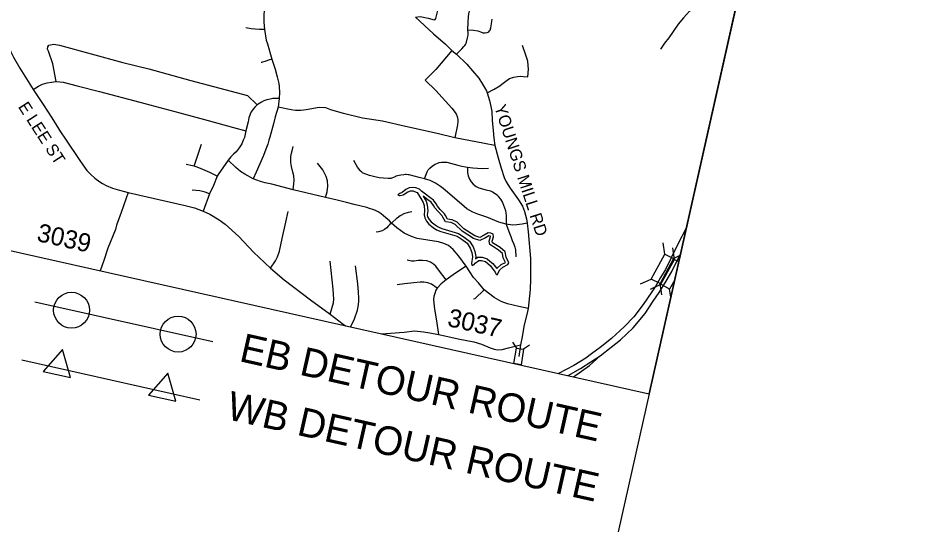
# Model space of a CAD drawing. Extents: x 1784499 to 1786147, y 841097 to 842538.
# Drawn here: x 1784767.1 to 1785099.6, y 841925.9 to 842114.2 of the extents above; entities that cross this region are included whole.
import ezdxf

# ---------------------------------------------------------------- set-up
doc = ezdxf.new("R2010")
doc.units = 0
for name, color, linetype in [('DEV CONE PLAN VIEW CELL', 7, 'Continuous'), ('Exist Hydrographic Buffer Line', 7, 'Continuous'), ('Exist Hydrographic Pond Over 1500 Sq Ft', 7, 'Continuous'), ('Exist Road Primary Interstate Divided Center Attributed', 7, 'Continuous'), ('Exist Road Primary Interstate Ramp 1 Lane Attributed', 7, 'Continuous'), ('Exist Road Primary Interstate Structure Standard Bridge CELL', 7, 'Continuous'), ('Exist Road Secondary Structure Standard Bridge CELL', 7, 'Continuous'), ('Exist Road Secondary Type 51 Attributed', 7, 'Continuous'), ('Exist Road Secondary Type 51 Number Label', 7, 'Continuous'), ('Old_Level_1', 7, 'Continuous'), ('Old_Level_40', 7, 'Continuous'), ('Prop DSN Text', 7, 'Continuous'), ('Scratch_Level_3', 7, 'Continuous')]:
    doc.layers.add(name, color=color, linetype=linetype)

msp = doc.modelspace()

# ---------------------------------------------------------------- linework, layer by layer
at = {"layer": 'DEV CONE PLAN VIEW CELL'}
for points in [[(1784783.32, 841992.77), (1784776.29, 841984.74), (1784786.25, 841982.51)], [(1784821.9, 841984.12), (1784814.88, 841976.09), (1784824.83, 841973.85)]]:
    msp.add_lwpolyline(points, close=True, dxfattribs=at)
at = {"layer": 'Exist Hydrographic Buffer Line'}
for points in [[(1784915.51, 842048.94), (1784916.53, 842047.14), (1784916.96, 842045.79), (1784917.14, 842043.62), (1784916.96, 842042.12), (1784917.12, 842041.38), (1784917.64, 842040.4), (1784918.38, 842039.53), (1784919.81, 842038.41), (1784920.91, 842037.68), (1784922.33, 842037.07), (1784928.39, 842035.33), (1784930.45, 842033.98), (1784932.41, 842032.52), (1784933.75, 842030.41), (1784934.4, 842028.66), (1784934.75, 842026.8), (1784934.63, 842025.95), (1784935.39, 842026.56), (1784937.08, 842026.6), (1784938.88, 842025.99), (1784939.86, 842025.19), (1784940.97, 842024.29), (1784942.44, 842022.43)], [(1784942.44, 842022.43), (1784943.99, 842023.88), (1784945.59, 842024.66), (1784944.83, 842026.32), (1784944.54, 842028), (1784943.05, 842029.21), (1784940.83, 842030.62), (1784939.92, 842031.22), (1784939.62, 842032.5), (1784940.14, 842034.12), (1784940.1, 842034.32), (1784940.02, 842034.35), (1784939.56, 842034.37), (1784938.28, 842033.64), (1784936.24, 842032.69), (1784933.97, 842033.49), (1784929.72, 842036.17), (1784927.24, 842038.56), (1784925.75, 842039.26), (1784923.69, 842039.59), (1784922.73, 842041.28), (1784922.4, 842041.81), (1784920.94, 842043.33), (1784919.78, 842044.64), (1784919.28, 842045.51), (1784918.43, 842046.72), (1784917.21, 842047.58), (1784915.51, 842048.94)]]:
    msp.add_lwpolyline(points, dxfattribs=at)
at = {"layer": 'Exist Hydrographic Pond Over 1500 Sq Ft'}
for points in [[(1784942.54, 842020.17), (1784943.53, 842021.95), (1784944.62, 842022.97), (1784946.47, 842023.87), (1784946.84, 842024.56), (1784945.88, 842026.64), (1784945.55, 842028.59), (1784943.69, 842030.1), (1784941.43, 842031.54), (1784940.89, 842031.9), (1784940.76, 842032.46), (1784941.28, 842034.05), (1784941.07, 842035.09), (1784940.28, 842035.44), (1784939.29, 842035.48), (1784937.78, 842034.62), (1784936.18, 842033.87), (1784934.45, 842034.48), (1784930.4, 842037.04), (1784927.87, 842039.47), (1784926.08, 842040.32), (1784924.38, 842040.59), (1784923.67, 842041.84), (1784923.27, 842042.48), (1784921.75, 842044.08), (1784920.67, 842045.29), (1784920.2, 842046.1), (1784919.22, 842047.51), (1784917.87, 842048.46), (1784916.35, 842049.66), (1784914.87, 842050.76), (1784914.07, 842051.53), (1784912.74, 842052.03), (1784911.68, 842052.18), (1784910.4, 842052.01), (1784909.17, 842051.39), (1784907.83, 842050.26), (1784906.87, 842049.98), (1784906.2, 842049.43)], [(1784906.2, 842049.43), (1784906.7, 842049.22), (1784907.05, 842049.24), (1784908.14, 842049.44), (1784909.88, 842050.59), (1784910.79, 842050.88), (1784911.78, 842050.86), (1784912.34, 842050.68), (1784913.24, 842050.25), (1784914.65, 842048.1), (1784915.47, 842046.67), (1784915.81, 842045.57), (1784915.98, 842043.64), (1784915.78, 842042.06), (1784916.03, 842040.98), (1784916.67, 842039.75), (1784917.57, 842038.69), (1784919.14, 842037.47), (1784920.36, 842036.66), (1784921.94, 842035.98), (1784927.9, 842034.26), (1784929.79, 842033.03), (1784931.55, 842031.71), (1784932.71, 842029.89), (1784933.28, 842028.35), (1784933.58, 842026.77), (1784933.23, 842024.26), (1784933.46, 842023.61), (1784934.12, 842023.9), (1784934.56, 842024.4), (1784935.81, 842025.41), (1784936.9, 842025.44), (1784938.31, 842024.96), (1784939.13, 842024.29), (1784940.14, 842023.47), (1784940.81, 842022.62), (1784941.5, 842021.6), (1784941.82, 842021.09), (1784942.13, 842020.54), (1784942.33, 842020.22), (1784942.54, 842020.17)]]:
    msp.add_lwpolyline(points, dxfattribs=at)
at = {"layer": 'Exist Road Primary Interstate Divided Center Attributed'}
for points in [[(1785012.01, 842037.78), (1785008.47, 842030.82), (1785004.27, 842022.12)], [(1785006.58, 842021.3), (1785009.52, 842027.3), (1785009.76, 842027.77)], [(1785004.27, 842022.12), (1785002.48, 842019.15), (1785000.75, 842016.15), (1784999.26, 842013.89), (1784996.05, 842009.32), (1784992.7, 842004.79), (1784989.25, 842001.17), (1784984.44, 841996.86), (1784980.33, 841993.45), (1784977.18, 841991.13)], [(1784980.27, 841990.44), (1784984.36, 841993.66), (1784987.81, 841996.36), (1784992.38, 842000.76), (1784996.76, 842005.93), (1784999.76, 842010.46), (1785001.95, 842013.63), (1785004.51, 842017.85), (1785006.58, 842021.3)], [(1784977.18, 841991.13), (1784975.12, 841989.61), (1784970.66, 841986.86), (1784965.08, 841983.98)], [(1784968.64, 841983.18), (1784973.14, 841985.83), (1784976.86, 841988.19), (1784980.27, 841990.44)]]:
    msp.add_lwpolyline(points, dxfattribs=at)
at = {"layer": 'Exist Road Primary Interstate Ramp 1 Lane Attributed'}
msp.add_lwpolyline([(1784970.55, 841982.75), (1784976.4, 841986.87), (1784980.27, 841990.44)], dxfattribs=at)
at = {"layer": 'Exist Road Primary Interstate Structure Standard Bridge CELL'}
for p, q in [((1785003.99, 842027.74), (1785003.34, 842031.84)), ((1784998.99, 842018.59), (1785003.97, 842027.75)), ((1785003.97, 842027.75), (1785007.23, 842026.09)), ((1785007.59, 842025.8), (1785006.99, 842029.98)), ((1785007.18, 842026.12), (1785009.65, 842027.29)), ((1785007.23, 842026.09), (1785002.25, 842016.94)), ((1784995.13, 842016.78), (1784998.99, 842018.59)), ((1785002.25, 842016.94), (1784998.99, 842018.59)), ((1784998.75, 842014.92), (1785002.58, 842016.66)), ((1785002.9, 842012.84), (1785002.25, 842016.94)), ((1785006.21, 842011.92), (1785005.78, 842014.89))]:
    msp.add_line(p, q, dxfattribs=at)
msp.add_lwpolyline([(1785007.64, 842018.3), (1785005.78, 842014.89), (1785002.58, 842016.66), (1785007.58, 842025.81), (1785009.13, 842024.96)], dxfattribs=at)
at = {"layer": 'Exist Road Secondary Structure Standard Bridge CELL'}
for p, q in [((1784948.14, 841995.43), (1784949.65, 841993.29)), ((1784954.43, 841994.36), (1784952.29, 841992.84)), ((1784951.32, 841987.19), (1784951.43, 841987.04))]:
    msp.add_line(p, q, dxfattribs=at)
msp.add_lwpolyline([(1784952.29, 841992.84), (1784951.33, 841987.19), (1784948.69, 841987.64), (1784949.65, 841993.29)], close=True, dxfattribs=at)
at = {"layer": 'Exist Road Secondary Type 51 Attributed'}
for p, q in [((1784925.93, 842102.29), (1784927.72, 842100.94)), ((1784862.72, 842084.78), (1784862.29, 842081.52)), ((1784846.01, 842074.14), (1784850.53, 842072.88)), ((1784831.62, 842059.92), (1784834.31, 842067.97)), ((1784837.24, 842049.76), (1784834.9, 842043.46))]:
    msp.add_line(p, q, dxfattribs=at)
for points in [[(1784912.65, 842114.61), (1784914.35, 842114.77), (1784917.28, 842114.21), (1784919.52, 842113.64), (1784919.88, 842113.72), (1784920.16, 842114.07), (1784921.76, 842120.45), (1784923.71, 842127.29), (1784925.34, 842133.03), (1784927.31, 842139.53), (1784930.73, 842152.55), (1784931.59, 842155.5)], [(1785019.82, 842129.73), (1785019.16, 842128.46), (1785018.05, 842125.95), (1785017.07, 842123.72), (1785016.25, 842121.67), (1785015.13, 842119.81), (1785013.01, 842116.7), (1785010.89, 842114.27), (1785008.94, 842112.04), (1785005.49, 842106.94), (1785003.91, 842105.07), (1785002.45, 842102.86)], [(1784858.84, 842124.15), (1784857.58, 842119.32), (1784857.25, 842117.35), (1784857.15, 842114.91), (1784857.13, 842112.67), (1784857.32, 842110.08)], [(1784931.84, 842109.88), (1784931.93, 842112.7), (1784932.07, 842114.67), (1784932.2, 842115.79), (1784932.64, 842117.74), (1784933.5, 842120.76)], [(1784912.65, 842114.61), (1784919.26, 842108.5), (1784923.63, 842104.7), (1784925.93, 842102.29)], [(1784931.84, 842109.88), (1784933.87, 842109.83), (1784935.48, 842109.49), (1784936.81, 842109.04), (1784937.37, 842108.85), (1784938.13, 842108.81), (1784938.9, 842108.91), (1784939.28, 842109.04), (1784939.53, 842109.22), (1784939.79, 842109.49), (1784939.98, 842109.79), (1784940.24, 842110.69), (1784940.45, 842112.06), (1784940.62, 842113.08), (1784940.7, 842113.78)], [(1784857.32, 842110.08), (1784855.49, 842110.08), (1784853.92, 842110.1), (1784852.41, 842110.22), (1784850.54, 842110.6)], [(1784762.82, 842109.22), (1784763.16, 842105.92), (1784763.27, 842104.98), (1784763.81, 842103.37), (1784764.37, 842101.84), (1784765.35, 842099.86), (1784767.74, 842095.87), (1784772.63, 842088.07)], [(1784857.32, 842110.08), (1784857.98, 842106.18), (1784858.4, 842104.73), (1784860.08, 842099.13)], [(1784927.72, 842100.94), (1784929.63, 842103.01), (1784930.38, 842103.77), (1784930.7, 842104.15), (1784930.99, 842104.57), (1784931.24, 842104.99), (1784931.38, 842105.39), (1784931.72, 842106.98), (1784931.9, 842107.97), (1784931.9, 842108.83), (1784931.84, 842109.88)], [(1784777.89, 842102.88), (1784777.96, 842103.65), (1784778.3, 842104.27), (1784780.16, 842104.64), (1784782.26, 842104.27), (1784805.39, 842097.99), (1784814.92, 842095.66), (1784830.41, 842091.35), (1784851.16, 842085.8), (1784854.65, 842082.48)], [(1784953.78, 842092.71), (1784954.01, 842095.52), (1784953.92, 842096.88), (1784953.77, 842098.39), (1784953.08, 842100.62), (1784951.81, 842104.21)], [(1784780.99, 842090.93), (1784779.85, 842097.49), (1784778.21, 842102.11), (1784777.89, 842102.88)], [(1784925.93, 842102.29), (1784920.17, 842095.38), (1784916.23, 842091.43)], [(1784927.72, 842100.94), (1784931.52, 842097.37), (1784933.58, 842094.89), (1784935.91, 842092.25), (1784937.26, 842090.04), (1784938.67, 842087.57), (1784938.97, 842086.83)], [(1784860.08, 842099.13), (1784858.76, 842098.77), (1784857.78, 842098.47), (1784856.29, 842097.95), (1784856.09, 842097.93)], [(1784860.08, 842099.13), (1784861.24, 842095.54), (1784862.03, 842092.69), (1784862.54, 842090.29), (1784862.74, 842089.13), (1784862.83, 842086.92), (1784862.72, 842084.78)], [(1784772.63, 842088.07), (1784774.51, 842089.24), (1784776.01, 842089.99), (1784777.71, 842090.46), (1784779.27, 842090.75), (1784780.99, 842090.93)], [(1784780.99, 842090.93), (1784782.36, 842090.89), (1784783.61, 842090.68), (1784788.67, 842089.38), (1784796.93, 842087.37), (1784811.61, 842083.36), (1784826.34, 842079.45), (1784836.75, 842076.64), (1784846.01, 842074.14)], [(1784916.23, 842091.43), (1784920.1, 842087.63), (1784925.93, 842081.26), (1784927.54, 842079.14), (1784927.97, 842078.1), (1784928.22, 842077.09), (1784928.23, 842076.33), (1784928.04, 842075.05), (1784927.12, 842070.33)], [(1784938.97, 842086.83), (1784941.44, 842088.13), (1784943.61, 842089.42), (1784944.33, 842089.99), (1784946.19, 842091.46), (1784947.16, 842092.03), (1784948.71, 842092.57), (1784950.05, 842092.81), (1784951.3, 842092.88), (1784952.18, 842092.87), (1784953.78, 842092.71)], [(1784772.63, 842088.07), (1784776.27, 842082.6), (1784779.47, 842077.62), (1784782.63, 842072.5), (1784784.46, 842069.87), (1784789.94, 842061.69), (1784792.29, 842058.35), (1784793.63, 842056.99), (1784795.18, 842055.53), (1784797, 842054.2), (1784798.05, 842053.6), (1784799.32, 842052.9), (1784801.69, 842051.89), (1784804.18, 842051.16), (1784806.05, 842050.63), (1784807.44, 842050.29)], [(1784862.72, 842084.78), (1784861.39, 842084.81), (1784860.35, 842084.71), (1784859.41, 842084.55), (1784858.24, 842084.28), (1784857.1, 842083.86), (1784856.27, 842083.44), (1784855.64, 842083.09), (1784854.65, 842082.48)], [(1784938.97, 842086.83), (1784939.83, 842084.01), (1784940.32, 842081.87), (1784940.57, 842079.97), (1784940.77, 842076.81), (1784941.07, 842072.98), (1784941.36, 842070.21), (1784941.75, 842067.55)], [(1784854.65, 842082.48), (1784853.76, 842081.57), (1784853.18, 842080.87), (1784852.45, 842079.83), (1784852.03, 842079.01), (1784851.61, 842077.69), (1784851.34, 842076.22), (1784850.53, 842072.88)], [(1784862.29, 842081.52), (1784861.28, 842077.99), (1784860.66, 842075.44), (1784859.33, 842070.61), (1784858.94, 842069.43), (1784858.52, 842067.98), (1784857.89, 842066.13), (1784856.98, 842063.86), (1784854.24, 842057.72), (1784853.22, 842055.34)], [(1784927.12, 842070.33), (1784920.6, 842071.89), (1784909.04, 842074.55), (1784900.56, 842076.39), (1784893.29, 842077.6), (1784886.34, 842079.23), (1784881.68, 842080.61), (1784879.85, 842081.36), (1784877.39, 842081.44), (1784872.65, 842080.56), (1784870.71, 842080.37), (1784868.67, 842080.41), (1784867.08, 842080.63), (1784862.29, 842081.52)], [(1784850.53, 842072.88), (1784849.97, 842070.48), (1784849.58, 842069.45), (1784849, 842068.15), (1784848.07, 842066.66), (1784846.91, 842065.24), (1784846.04, 842064.29), (1784845.04, 842063.33), (1784843.97, 842062.12)], [(1784941.75, 842067.55), (1784937.99, 842068.25), (1784927.12, 842070.33)], [(1784941.75, 842067.55), (1784942.93, 842062.95), (1784943.99, 842059.24), (1784945.12, 842055.81), (1784945.83, 842054.23), (1784947.37, 842051.86), (1784950.37, 842047.65), (1784951.9, 842045.35), (1784952.65, 842043.37), (1784953.33, 842040.65), (1784953.55, 842039.09)], [(1784867.82, 842051.34), (1784868.12, 842053.53), (1784868.2, 842054.67), (1784868.1, 842056.35), (1784867.75, 842057.72), (1784867.28, 842059.83), (1784867, 842061.27), (1784866.97, 842062.42), (1784867.01, 842063.53), (1784867.24, 842064.76), (1784867.49, 842065.55), (1784867.88, 842067.11)], [(1784831.62, 842059.92), (1784830.98, 842060.12), (1784828.61, 842060.61)], [(1784843.97, 842062.12), (1784840.34, 842056.86), (1784840.05, 842056.23)], [(1784853.22, 842055.34), (1784851.25, 842056.41), (1784850.12, 842057.06), (1784848.56, 842058), (1784846.85, 842059.41), (1784843.97, 842062.12)], [(1784879.72, 842048.42), (1784880.26, 842050.59), (1784880.53, 842052.68), (1784880.41, 842054.53), (1784879.9, 842056.19), (1784878.68, 842058.56), (1784876.74, 842061.01)], [(1784915.98, 842055.36), (1784914.04, 842055.85), (1784910.38, 842056.73), (1784910.01, 842056.79), (1784909.22, 842056.85), (1784908.82, 842056.86), (1784908.34, 842056.82), (1784907.23, 842056.61), (1784906.07, 842056.37), (1784905.63, 842056.25), (1784905.17, 842056.08), (1784904.02, 842055.59), (1784903.85, 842055.54), (1784903.59, 842055.49), (1784903.06, 842055.44), (1784902.59, 842055.45), (1784900.96, 842055.52), (1784899.4, 842055.68), (1784897.8, 842055.99), (1784895.78, 842056.55), (1784893.54, 842057.34), (1784893.29, 842057.5), (1784893.03, 842057.7), (1784892.54, 842058.13), (1784892.38, 842058.32), (1784891.45, 842059.64), (1784890.09, 842061.97)], [(1784915.98, 842055.36), (1784916.91, 842057.83), (1784917.34, 842058.55), (1784917.95, 842059.26), (1784918.87, 842060.1), (1784919.83, 842060.71), (1784920.49, 842060.99), (1784921.32, 842061.24), (1784922.19, 842061.44), (1784923.21, 842061.48), (1784924.17, 842061.4), (1784925.47, 842061.09), (1784928.16, 842060.26), (1784929.58, 842059.94), (1784930.98, 842059.67), (1784931.69, 842059.56)], [(1784840.05, 842056.23), (1784837.26, 842057.63), (1784834.71, 842058.74), (1784832.69, 842059.58), (1784831.62, 842059.92)], [(1784931.69, 842059.56), (1784931.66, 842057.6), (1784931.92, 842056.4), (1784932.43, 842055.14), (1784933.06, 842054.18), (1784933.8, 842053.39), (1784934.86, 842052.52), (1784935.87, 842052.01), (1784937.15, 842051.61), (1784938.48, 842051.34), (1784939.62, 842051.08), (1784940.2, 842050.88), (1784940.82, 842050.58), (1784941.8, 842049.99)], [(1784931.69, 842059.56), (1784933.68, 842059.38), (1784937.05, 842059.11), (1784939.45, 842059.23)], [(1784840.05, 842056.23), (1784838.68, 842052.92), (1784837.24, 842049.76)], [(1784860, 842053.34), (1784857.58, 842053.89), (1784855.86, 842054.35), (1784853.22, 842055.34)], [(1784945.9, 842038.66), (1784943.19, 842039.48), (1784938.78, 842041.22), (1784935.51, 842042.35), (1784933.7, 842043.11), (1784932.59, 842043.67), (1784931.49, 842044.35), (1784930.44, 842045.16), (1784924.36, 842050.48), (1784922.74, 842051.82), (1784921.85, 842052.49), (1784920.74, 842053.25), (1784919.97, 842053.71), (1784919.28, 842054.13), (1784918.79, 842054.36), (1784917.98, 842054.69), (1784915.98, 842055.36)], [(1784837.24, 842049.76), (1784835.56, 842050.4), (1784833.62, 842050.95), (1784832.17, 842051.05), (1784830.9, 842051.1)], [(1784867.82, 842051.34), (1784860, 842053.34)], [(1784879.72, 842048.42), (1784867.82, 842051.34)], [(1784807.44, 842050.29), (1784804.84, 842042.95), (1784803.13, 842038.3), (1784802.7, 842036.76), (1784799.98, 842029.88), (1784798.48, 842025.44), (1784797.17, 842021.63)], [(1784807.44, 842050.29), (1784828.32, 842045.58), (1784831.64, 842044.69), (1784834.9, 842043.46)], [(1784903.91, 842039.07), (1784903.14, 842039.86), (1784901.81, 842041.06), (1784900.1, 842042.46), (1784899.02, 842043.22), (1784898.28, 842043.61), (1784897.42, 842043.98), (1784895.86, 842044.5), (1784894.84, 842044.83), (1784890.17, 842045.94), (1784887.39, 842046.59), (1784883.91, 842047.48), (1784879.72, 842048.42)], [(1784941.8, 842049.99), (1784942.19, 842049.72), (1784942.69, 842049.29), (1784942.98, 842048.81), (1784943.77, 842047.8), (1784944.5, 842046.62), (1784944.94, 842045.67), (1784945.29, 842044.64), (1784945.6, 842043.67), (1784945.75, 842042.78), (1784945.88, 842042), (1784945.89, 842041.25), (1784945.92, 842040.38), (1784945.9, 842038.66)], [(1784834.9, 842043.46), (1784837.29, 842042.4), (1784840.75, 842040.29), (1784842.92, 842038.71), (1784847.88, 842034.13), (1784853.3, 842028.42), (1784859.49, 842022.62)], [(1784859.49, 842022.62), (1784861.4, 842025.24), (1784862.15, 842026.72), (1784862.81, 842028.75), (1784863.86, 842033.42), (1784865.14, 842039.39), (1784866.03, 842043.36)], [(1784903.91, 842039.07), (1784905.95, 842040.99), (1784907.01, 842041.82), (1784907.37, 842041.99), (1784908.53, 842042.56), (1784910.07, 842043.15), (1784911.34, 842043.29)], [(1784903.91, 842039.07), (1784903.15, 842038.45), (1784902.7, 842037.94), (1784902.1, 842037.34), (1784901.36, 842036.76), (1784900.51, 842036.28), (1784899.05, 842035.84), (1784898.24, 842035.78)], [(1784931.27, 842023.36), (1784928.49, 842027.03), (1784926.52, 842029.38), (1784924.72, 842030.82), (1784923.05, 842031.67), (1784921.11, 842032.27), (1784913.31, 842033.49), (1784911.15, 842034.13), (1784908.52, 842035.41), (1784905.8, 842037.31), (1784903.91, 842039.07)], [(1784953.55, 842039.09), (1784951.74, 842038.74), (1784949.74, 842038.42), (1784948.16, 842038.37), (1784945.9, 842038.66)], [(1784945.9, 842038.66), (1784946.81, 842035.95), (1784947.53, 842034.13), (1784948.1, 842032.7), (1784948.64, 842031.32), (1784949.03, 842030.25), (1784949.31, 842029.29), (1784949.44, 842026.67)], [(1784953.55, 842039.09), (1784954, 842035.85), (1784954.84, 842026.13), (1784954.85, 842018.56), (1784954.65, 842014.7), (1784953.89, 842007.78)], [(1784881.42, 842005.73), (1784882.65, 842009.93), (1784882.72, 842011.22), (1784882.46, 842014.89), (1784881.42, 842025.1)], [(1784923.84, 842018.25), (1784921.44, 842021.49), (1784920.13, 842023.3), (1784919.25, 842024.09), (1784918.1, 842024.81), (1784916.81, 842025.23), (1784915.28, 842025.44), (1784913.61, 842025.35), (1784912.18, 842025.15), (1784911.2, 842025.17), (1784909.57, 842025.53)], [(1784859.49, 842022.62), (1784864.49, 842018.27), (1784874.22, 842011.03), (1784881.42, 842005.73)], [(1784888.8, 842001.08), (1784889.88, 842002.88), (1784890.32, 842004.06), (1784891.44, 842007.24), (1784891.81, 842009.13), (1784891.95, 842010.55), (1784891.9, 842011.61), (1784891.8, 842013.78), (1784891.51, 842016.86), (1784890.66, 842023.44)], [(1784931.27, 842023.36), (1784927.35, 842020.69), (1784923.84, 842018.25)], [(1784937.88, 842014.62), (1784935.72, 842017.15), (1784933.97, 842019.14), (1784931.27, 842023.36)], [(1784920.6, 842015.23), (1784918.53, 842016.75), (1784917.13, 842017.26), (1784915.72, 842017.44), (1784914.4, 842017.41), (1784912.11, 842017.2), (1784908.68, 842016.85), (1784905.96, 842016.47)], [(1784923.84, 842018.25), (1784922.07, 842016.81), (1784920.6, 842015.23)], [(1784920.6, 842015.23), (1784920.12, 842014.55), (1784919.7, 842013.26), (1784919.39, 842012.21), (1784919.27, 842011.05), (1784919.38, 842009.78), (1784919.68, 842007.6), (1784920.35, 842003.24), (1784921.07, 841998.27)], [(1784937.88, 842014.62), (1784934.34, 842011.38), (1784933.94, 842011.16)], [(1784953.89, 842007.78), (1784950.49, 842008.54), (1784946.37, 842009.47), (1784944.05, 842010.35), (1784941.49, 842011.82), (1784937.88, 842014.62)], [(1784953.89, 842007.78), (1784953.73, 842006.66), (1784952.39, 842001.17), (1784951.77, 841997.4), (1784951.12, 841994.42)], [(1784881.42, 842005.73), (1784886.16, 842002.09), (1784886.97, 842001.49)], [(1784900.22, 841998.52), (1784908.49, 841999.11), (1784912.33, 841999.56), (1784915.55, 841999.3), (1784917.89, 841998.87), (1784921.07, 841998.27)], [(1784921.07, 841998.27), (1784923.45, 841997.81), (1784928.26, 841996.73), (1784934, 841995.54), (1784936.81, 841994.72), (1784940.07, 841993.43), (1784941.49, 841992.86), (1784942.67, 841992.65), (1784944.4, 841992.73), (1784946.78, 841993.43), (1784951.12, 841994.42)], [(1784951.12, 841994.42), (1784950.46, 841990.21)]]:
    msp.add_lwpolyline(points, dxfattribs=at)
at = {"layer": 'Old_Level_1'}
for p, q in [((1784838.39, 841995.53), (1784773.24, 842010.15)), ((1784833.6, 841974.2), (1784768.45, 841988.81))]:
    msp.add_line(p, q, dxfattribs=at)
at = {"layer": 'Old_Level_40'}
msp.add_line((1785099.64, 842428.53), (1784986.93, 841925.94), dxfattribs=at)
at = {"layer": 'Prop DSN Text'}
for centre in [(1784786.65, 842007.16), (1784825.68, 841998.41)]:
    msp.add_circle(centre, 6.57, dxfattribs=at)
at = {"layer": 'Scratch_Level_3'}
msp.add_lwpolyline([(1785039.41, 842390.83), (1785050.23, 842439.1), (1784611.48, 842537.49), (1784510.23, 842085.98), (1784998.27, 841976.54), (1785088.7, 842379.78)], close=True, dxfattribs=at)

# ---------------------------------------------------------------- texts
at = {"layer": 'Exist Road Secondary Type 51 Number Label'}
for s, p in [('3039', (1784773.6, 842032.58)), ('3037', (1784924.02, 842001.42))]:
    msp.add_text(s, height=6.665, rotation=347.3599, dxfattribs=at).set_placement(p)
at = {"layer": 'Old_Level_1'}
for s, p in [('EB DETOUR ROUTE', (1784847.72, 841988.56)), ('WB DETOUR ROUTE', (1784842.96, 841967.37))]:
    msp.add_text(s, height=10.5, rotation=347.336, dxfattribs=at).set_placement(p)
at = {"layer": 'Prop DSN Text'}
for s, height, rotation, p in [('E LEE ST', 4.397, 302.8901, (1784766.91, 842081.73)), ('YOUNGS MILL RD', 4.3971, 288.0062, (1784941.48, 842081.72))]:
    msp.add_text(s, height=height, rotation=rotation, dxfattribs=at).set_placement(p)

doc.saveas('drawing.dxf')
